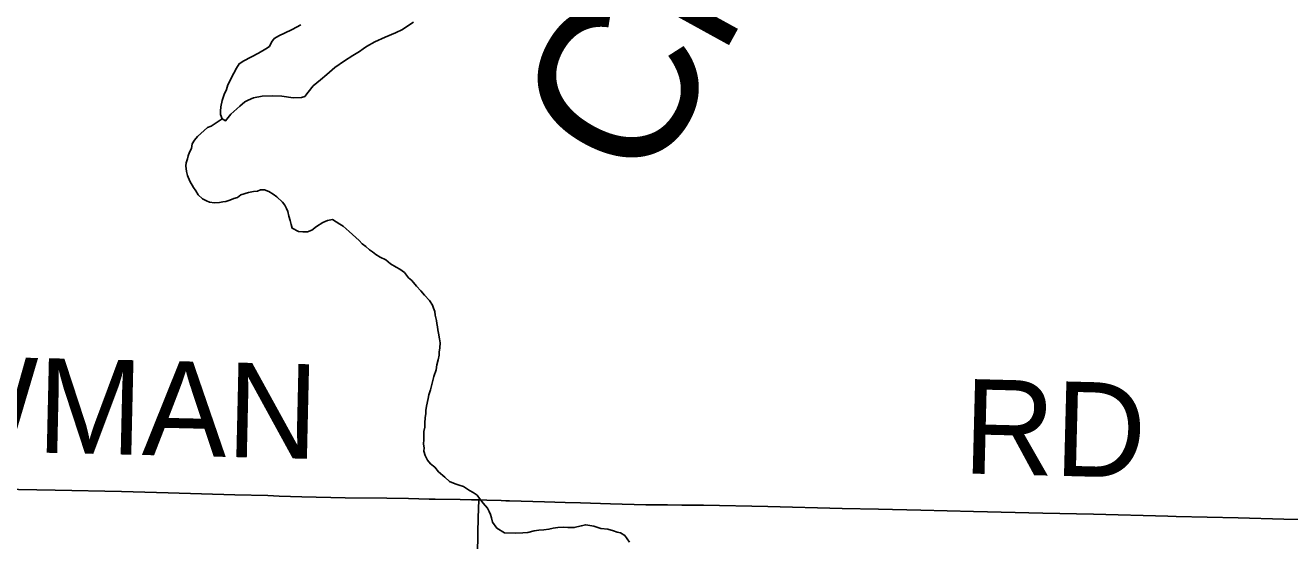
# Model space of a CAD drawing. Extents: x -483 to 680, y 0 to 440.
# Drawn here: x 186.57 to 224.56, y 174.97 to 190.46 of the extents above; entities that cross this region are included whole.
import ezdxf

# ---------------------------------------------------------------- set-up
doc = ezdxf.new("R2010")
doc.units = 0
for name, color, linetype in [('GM_X_Minor_Lake', 7, 'Continuous'), ('GM_X_Minor_River', 7, 'Continuous'), ('GM_X_Minor_River_Text', 7, 'Continuous'), ('GM_X_Township_Road', 7, 'Continuous'), ('GM_X_Township_Road_Text', 7, 'Continuous')]:
    doc.layers.add(name, color=color, linetype=linetype)

msp = doc.modelspace()

# ---------------------------------------------------------------- linework, layer by layer
at = {"layer": 'GM_X_Minor_Lake'}
msp.add_lwpolyline([(194.845, 190.477), (194.593, 190.334), (194.361, 190.227), (194.206, 190.156), (194.051, 190.066), (193.971, 189.955), (193.91, 189.823), (193.793, 189.751), (193.58, 189.625), (193.135, 189.393), (192.998, 189.302), (192.918, 189.171), (192.837, 189.022), (192.776, 188.91), (192.715, 188.779), (192.654, 188.667), (192.612, 188.535), (192.55, 188.385), (192.487, 188.197), (192.443, 188.008), (192.439, 187.875), (192.436, 187.78), (192.488, 187.645), (192.582, 187.585), (192.741, 187.789), (193.015, 188.027), (193.171, 188.155), (193.268, 188.209), (193.423, 188.28), (193.691, 188.328), (193.996, 188.337), (194.281, 188.327), (194.622, 188.278), (194.87, 188.289), (194.967, 188.324), (195.066, 188.454), (195.224, 188.639), (195.44, 188.822), (195.635, 188.986), (195.87, 189.188), (196.162, 189.388), (196.415, 189.55), (196.609, 189.677), (196.726, 189.749), (196.824, 189.822), (197.076, 189.966), (197.385, 190.108), (197.693, 190.231), (197.906, 190.338), (198.062, 190.447), (198.237, 190.555)], dxfattribs=at)
msp.add_lwpolyline([(194.845, 190.477), (194.593, 190.334), (194.361, 190.227), (194.206, 190.156), (194.051, 190.066), (193.971, 189.955), (193.91, 189.823), (193.793, 189.751), (193.58, 189.625), (193.135, 189.393), (192.998, 189.302), (192.918, 189.171), (192.837, 189.022), (192.776, 188.91), (192.715, 188.779), (192.654, 188.667), (192.612, 188.535), (192.55, 188.385), (192.487, 188.197), (192.443, 188.008), (192.439, 187.875), (192.436, 187.78), (192.488, 187.645), (192.582, 187.585), (192.741, 187.789), (193.015, 188.027), (193.171, 188.155), (193.268, 188.209), (193.423, 188.28), (193.691, 188.328), (193.996, 188.337), (194.281, 188.327), (194.622, 188.278), (194.87, 188.289), (194.967, 188.324), (195.066, 188.454), (195.224, 188.639), (195.44, 188.822), (195.635, 188.986), (195.87, 189.188), (196.162, 189.388), (196.415, 189.55), (196.609, 189.677), (196.726, 189.749), (196.824, 189.822), (197.076, 189.966), (197.385, 190.108), (197.693, 190.231), (197.906, 190.338), (198.062, 190.447), (198.237, 190.555)], dxfattribs=at)
at = {"layer": 'GM_X_Minor_River'}
for points in [[(192.488, 187.645), (192.158, 187.428), (192.042, 187.393), (191.944, 187.301), (191.846, 187.21), (191.748, 187.118), (191.649, 187.007), (191.588, 186.895), (191.565, 186.762), (191.505, 186.65), (191.463, 186.537), (191.441, 186.443), (191.399, 186.33), (191.396, 186.235), (191.41, 186.064), (191.444, 185.948), (191.515, 185.775), (191.623, 185.581), (191.696, 185.483), (191.768, 185.367), (191.898, 185.248), (192.01, 185.188), (192.104, 185.147), (192.256, 185.122), (192.408, 185.136), (192.504, 185.152), (192.6, 185.168), (192.715, 185.202), (192.831, 185.256), (192.946, 185.29), (193.044, 185.363), (193.275, 185.431), (193.428, 185.464), (193.543, 185.479), (193.639, 185.514), (193.753, 185.511), (193.885, 185.468), (194.016, 185.388), (194.128, 185.308), (194.294, 185.15), (194.367, 185.053), (194.421, 184.956), (194.456, 184.86), (194.49, 184.725), (194.524, 184.591), (194.558, 184.476), (194.592, 184.36), (194.78, 184.259), (194.913, 184.255), (195.046, 184.25), (195.181, 184.303), (195.318, 184.413), (195.512, 184.539), (195.647, 184.592), (195.801, 184.625), (196.025, 184.484), (196.118, 184.424), (196.303, 184.266), (196.599, 183.99), (196.691, 183.892), (196.803, 183.812), (196.914, 183.713), (197.007, 183.653), (197.1, 183.574), (197.231, 183.493), (197.399, 183.412), (197.548, 183.293), (197.716, 183.192), (197.828, 183.131), (197.959, 183.032), (198.087, 182.875), (198.18, 182.796), (198.326, 182.62), (198.455, 182.483), (198.565, 182.346), (198.712, 182.189), (198.803, 182.053), (198.838, 181.956), (198.873, 181.86), (198.889, 181.745), (198.922, 181.592), (198.938, 181.497), (198.954, 181.401), (198.97, 181.305), (198.986, 181.21), (199.018, 181.037), (199.034, 180.923), (199.029, 180.771), (199.006, 180.638), (199.003, 180.543), (198.979, 180.411), (198.936, 180.26), (198.913, 180.109), (198.849, 179.902), (198.741, 179.506), (198.698, 179.355), (198.675, 179.241), (198.63, 179.015), (198.607, 178.882)], [(198.607, 178.882), (198.604, 178.787), (198.581, 178.674), (198.576, 178.503), (198.572, 178.389), (198.549, 178.256), (198.544, 178.104), (198.541, 178.009), (198.537, 177.876), (198.552, 177.762), (198.549, 177.667), (198.583, 177.532), (198.655, 177.397), (198.746, 177.28), (198.876, 177.18), (198.986, 177.044), (199.171, 176.885), (199.319, 176.747), (199.489, 176.685), (199.602, 176.643), (199.734, 176.6), (199.92, 176.48), (200.032, 176.419), (200.144, 176.339), (200.217, 176.242), (200.327, 176.105), (200.455, 175.949), (200.509, 175.852), (200.544, 175.756), (200.579, 175.659), (200.613, 175.525), (200.741, 175.35), (200.965, 175.209), (201.288, 175.198), (201.517, 175.21), (201.67, 175.224), (201.862, 175.274), (201.996, 175.289), (202.149, 175.303), (202.301, 175.317), (202.436, 175.351), (202.57, 175.365), (202.741, 175.379), (202.874, 175.374), (202.97, 175.371), (203.065, 175.368), (203.276, 175.418), (203.41, 175.452), (203.656, 175.405), (203.864, 175.341), (204.072, 175.316), (204.242, 175.272), (204.355, 175.23), (204.45, 175.208), (204.58, 175.128), (204.727, 174.933)]]:
    msp.add_lwpolyline(points, dxfattribs=at)
at = {"layer": 'GM_X_Township_Road'}
for points in [[(174.945, 176.774), (176.033, 176.744), (178.345, 176.681), (179.775, 176.646), (180.375, 176.633), (181.856, 176.601), (183.621, 176.563), (185.812, 176.524), (187.465, 176.489), (189.461, 176.447), (190.861, 176.407), (192.865, 176.349), (193.855, 176.327), (194.197, 176.315), (194.88, 176.294), (196.185, 176.261), (197.429, 176.248), (198.081, 176.236), (198.702, 176.222), (198.889, 176.217), (199.633, 176.208), (199.974, 176.204), (200.193, 176.2)], [(200.154, 174.536), (200.17, 175.211), (200.18, 175.664), (200.193, 176.2)], [(200.193, 176.2), (200.438, 176.195), (200.865, 176.18), (201.009, 176.173), (201.124, 176.173), (202.17, 176.142), (202.792, 176.121), (203.257, 176.106), (204.158, 176.077), (205.214, 176.052), (205.555, 176.048), (205.71, 176.047), (205.865, 176.048), (206.299, 176.042), (206.952, 176.037), (208.878, 176.001), (211.115, 175.944), (212.203, 175.921), (213.477, 175.89), (215.066, 175.851), (217.142, 175.799), (218.665, 175.768), (220.902, 175.71), (221.151, 175.704), (223.015, 175.658), (224.382, 175.624), (225.006, 175.605)]]:
    msp.add_lwpolyline(points, dxfattribs=at)

# ---------------------------------------------------------------- texts
at = {"layer": 'GM_X_Minor_River_Text'}
msp.add_text('Creek', height=4.7376, rotation=61.175, dxfattribs=at).set_placement((205.298, 185.471))
at = {"layer": 'GM_X_Township_Road_Text'}
for s, rotation, p in [('BOWMAN', 358.6797, (177.83, 177.831)), ('RD', 358.5311, (214.726, 176.996))]:
    msp.add_text(s, height=2.8409, rotation=rotation, dxfattribs=at).set_placement(p)

doc.saveas('drawing.dxf')
